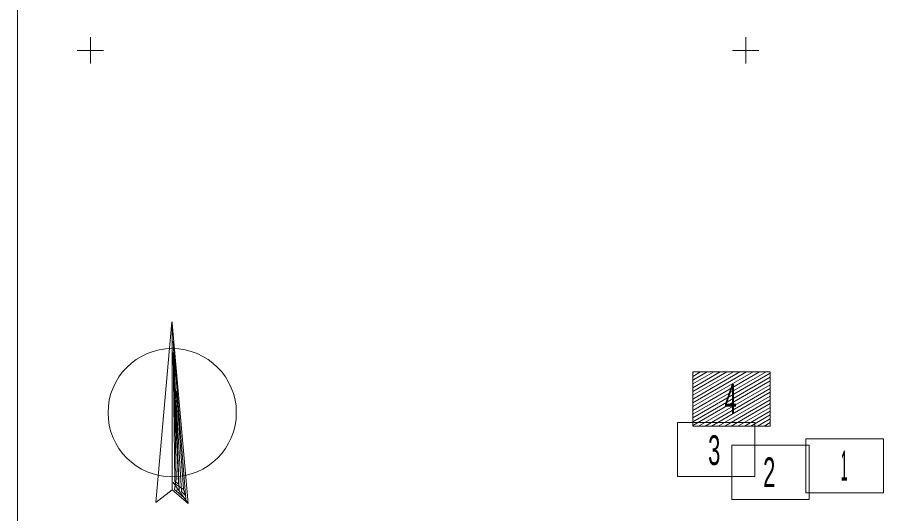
# Model space of a CAD drawing. Extents: x -670514 to -669423, y -1130798 to -1130123.
# Drawn here: x -670405.6 to -670338.2, y -1130235.4 to -1130197.5 of the extents above; entities that cross this region are included whole.
import ezdxf
from ezdxf.enums import TextEntityAlignment as Align

# ---------------------------------------------------------------- set-up
doc = ezdxf.new("R2010")
doc.units = 0
doc.header["$LTSCALE"] = 0.24
doc.layers.add('60', color=7, linetype='Continuous', lineweight=13)
doc.layers.add('61', color=7, linetype='Continuous', lineweight=13)

msp = doc.modelspace()

# ---------------------------------------------------------------- linework, layer by layer
at = {"layer": '60'}
msp.add_lwpolyline([(-670405.553, -1130409.706), (-669995.553, -1130409.706), (-669995.553, -1130122.706), (-670405.553, -1130122.706)], close=True, dxfattribs=at)
at = {"layer": '61'}
for p, q in [((-670400, -1130199), (-670400, -1130201)), ((-670350, -1130199), (-670350, -1130201)), ((-670401, -1130200), (-670399, -1130200)), ((-670351, -1130200), (-670349, -1130200)), ((-670394.998, -1130234.516), (-670393.793, -1130220.738)), ((-670393.763, -1130233.563), (-670393.763, -1130220.732)), ((-670392.552, -1130234.603), (-670393.759, -1130220.825)), ((-670354.028, -1130224.605), (-670353.945, -1130224.557)), ((-670354.028, -1130224.894), (-670353.445, -1130224.557)), ((-670354.028, -1130225.182), (-670352.945, -1130224.557)), ((-670354.028, -1130225.471), (-670352.445, -1130224.557)), ((-670354.028, -1130225.76), (-670351.945, -1130224.557)), ((-670354.028, -1130226.048), (-670351.445, -1130224.557)), ((-670354.028, -1130226.337), (-670350.945, -1130224.557)), ((-670354.028, -1130226.626), (-670350.445, -1130224.557)), ((-670354.028, -1130226.914), (-670349.945, -1130224.557)), ((-670354.028, -1130227.203), (-670349.445, -1130224.557)), ((-670354.028, -1130227.492), (-670348.945, -1130224.557)), ((-670354.028, -1130227.78), (-670348.445, -1130224.557)), ((-670354.028, -1130228.069), (-670348.124, -1130224.66)), ((-670354.028, -1130228.358), (-670348.124, -1130224.949)), ((-670354.028, -1130228.646), (-670348.124, -1130225.238)), ((-670353.604, -1130228.69), (-670348.124, -1130225.526)), ((-670353.104, -1130228.69), (-670348.124, -1130225.815)), ((-670352.604, -1130228.69), (-670348.124, -1130226.104)), ((-670352.104, -1130228.69), (-670348.124, -1130226.392)), ((-670351.604, -1130228.69), (-670348.124, -1130226.681)), ((-670351.104, -1130228.69), (-670348.124, -1130226.97)), ((-670350.604, -1130228.69), (-670348.124, -1130227.258)), ((-670350.104, -1130228.69), (-670348.124, -1130227.547)), ((-670349.604, -1130228.69), (-670348.124, -1130227.836)), ((-670349.104, -1130228.69), (-670348.124, -1130228.124)), ((-670348.604, -1130228.69), (-670348.124, -1130228.413))]:
    msp.add_line(p, q, dxfattribs=at)
for points in [[(-670393.68, -1130222.198), (-670392.72, -1130234.279), (-670393.579, -1130233.521), (-670393.452, -1130232.737), (-670393.654, -1130222.299), (-670393.225, -1130233.571), (-670393.427, -1130233.546)], [(-670394.998, -1130234.516), (-670393.763, -1130233.563), (-670392.552, -1130234.603), (-670393.698, -1130232.991), (-670392.891, -1130233.541), (-670392.725, -1130234.022), (-670393.056, -1130233.678), (-670393.68, -1130223.068), (-670393.57, -1130232.923), (-670393.276, -1130233.094), (-670393.533, -1130227.086), (-670393.423, -1130226.021), (-670392.909, -1130233.472)]]:
    msp.add_lwpolyline(points, dxfattribs=at)
for points in [[(-670354.028, -1130228.69), (-670348.124, -1130228.69), (-670348.124, -1130224.557), (-670354.028, -1130224.557)], [(-670355.199, -1130232.535), (-670349.295, -1130232.535), (-670349.295, -1130228.402), (-670355.199, -1130228.402)], [(-670351.054, -1130234.284), (-670345.15, -1130234.284), (-670345.15, -1130230.151), (-670351.054, -1130230.151)], [(-670345.402, -1130233.785), (-670339.498, -1130233.785), (-670339.498, -1130229.652), (-670345.402, -1130229.652)]]:
    msp.add_lwpolyline(points, close=True, dxfattribs=at)
msp.add_circle((-670393.763, -1130227.668), 4.8953, dxfattribs=at)

# ---------------------------------------------------------------- texts
for s, width, p in [('4', 0.55, (-670351.1542, -1130227.7309)), ('3', 0.55, (-670352.4042, -1130231.6599)), ('1', 0.3, (-670342.4942, -1130232.844)), ('2', 0.55, (-670348.2082, -1130233.3499))]:
    msp.add_text(s, height=2.268, rotation=0.009, dxfattribs=dict(at, width=width)).set_placement(p, align=Align.CENTER)

doc.saveas('drawing.dxf')
